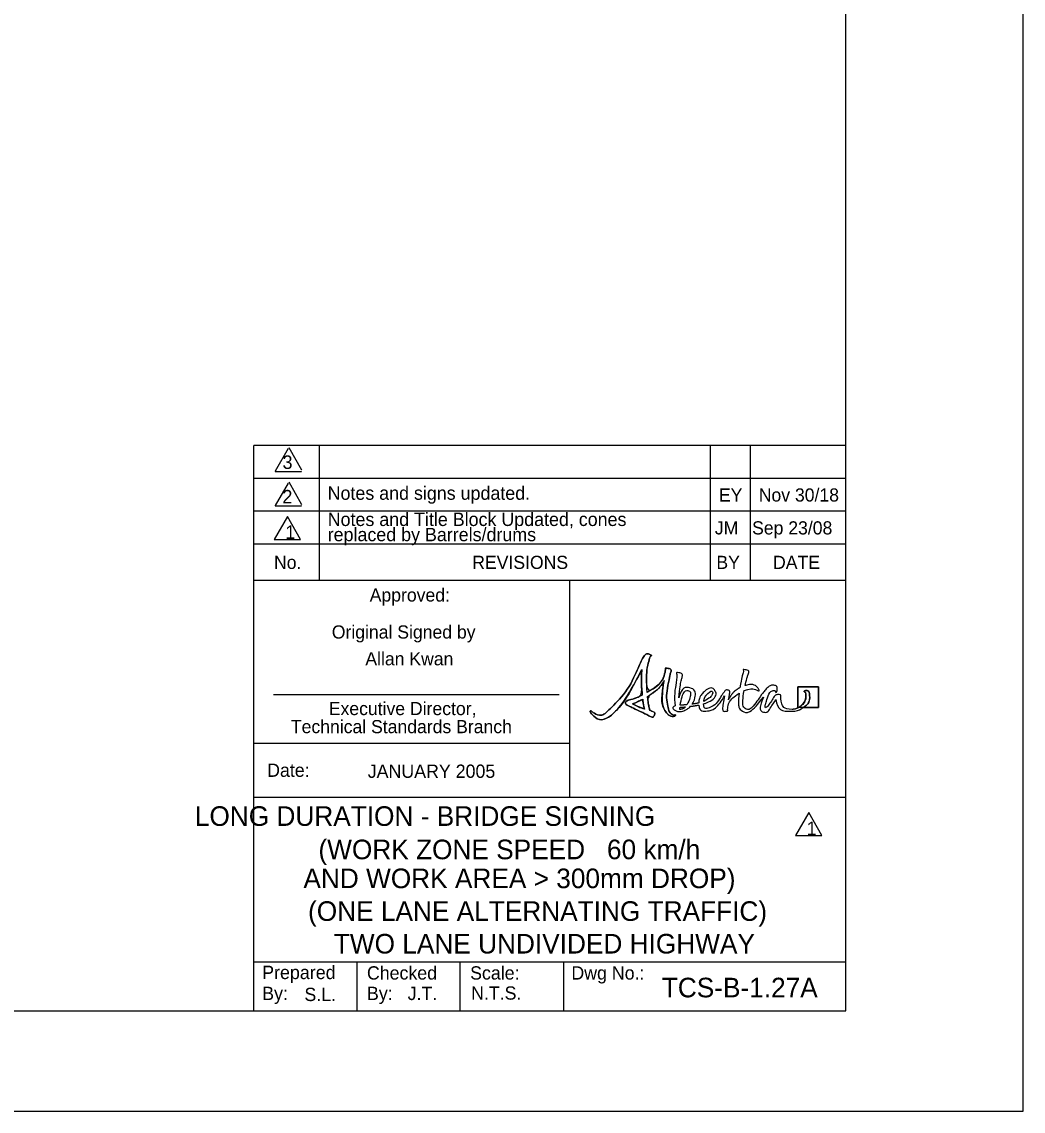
# Model space of a CAD drawing. Extents: x 2179 to 2395, y 134 to 413.
# Drawn here: x 2286.7 to 2394.7, y 133.8 to 251.3 of the extents above; entities that cross this region are included whole.
import ezdxf

# ---------------------------------------------------------------- set-up
doc = ezdxf.new("R2010")
doc.units = 0
for name, color, linetype in [('approved by', 7, 'Continuous'), ('Level 1', 7, 'Continuous'), ('Level 22', 7, 'Continuous'), ('Level 44', 7, 'Continuous'), ('Level 45', 7, 'Continuous'), ('Level 53', 7, 'Continuous'), ('Level 60', 7, 'Continuous'), ('Level 63', 7, 'Continuous'), ('Level 7', 7, 'Continuous')]:
    doc.layers.add(name, color=color, linetype=linetype)

# ---------------------------------------------------------------- blocks, each defined once
blk = doc.blocks.new('REV1')
at = {"layer": 'Level 1'}
blk.add_lwpolyline([(0.114, 1.689), (-1.305, -0.781), (1.533, -0.781)], close=True, dxfattribs=at)
blk.add_text('1', height=1.448, rotation=360, dxfattribs=at).set_placement((-0.113, -0.724))

msp = doc.modelspace()

# ---------------------------------------------------------------- linework, layer by layer
at = {"layer": 'Level 1'}
for p, q in [((2311.78, 144.57), (2311.78, 191.03)), ((2345.83, 191.03), (2345.83, 167.62)), ((2311.78, 173.47), (2345.83, 173.47)), ((2311.78, 167.62), (2375.62, 167.62)), ((2311.78, 149.89), (2375.62, 149.89)), ((2322.91, 144.57), (2322.91, 149.89)), ((2334.04, 144.57), (2334.04, 149.89)), ((2345.17, 149.89), (2345.17, 144.57))]:
    msp.add_line(p, q, dxfattribs=at)
at = {"layer": 'Level 22'}
msp.add_line((2327.24, 144.57), (2327.24, 144.57), dxfattribs=at)
at = {"layer": 'Level 44'}
for p, q in [((2375.65, 205.58), (2311.77, 205.58)), ((2375.65, 202.03), (2311.77, 202.03)), ((2375.65, 198.48), (2311.77, 198.48)), ((2375.65, 194.93), (2311.77, 194.93)), ((2311.78, 191.03), (2375.65, 191.03))]:
    msp.add_line(p, q, dxfattribs=at)
msp.add_lwpolyline([(2315.4, 197.91), (2313.98, 195.44), (2316.82, 195.44)], close=True, dxfattribs=at)
at = {"layer": 'Level 45'}
msp.add_line((2345.85, 191.03), (2345.85, 191.03), dxfattribs=at)
at = {"layer": 'Level 53'}
msp.add_line((2371.06, 177.31), (2370.51, 177.31), dxfattribs=at)
msp.add_lwpolyline([(2371.06, 177.31), (2372.67, 177.31), (2372.67, 179.54), (2370.44, 179.54), (2370.44, 177.31), (2370.51, 177.31)], dxfattribs=at)
for points, degree in [([(2357.07, 176.5), (2356.83, 176.53), (2356.52, 176.86), (2356.42, 177.4), (2356.25, 178.36), (2356.35, 179.32), (2356.64, 180.74), (2356.69, 181.01), (2356.87, 181.47), (2356.29, 181.56), (2356.1, 181.59), (2356.2, 181.5), (2356.15, 181.26), (2355.92, 180.2), (2355.06, 179.43), (2354.19, 178.92), (2354.1, 180.13), (2354.14, 181.48), (2354.36, 182.31), (2354.56, 183), (2354.79, 182.87), (2354.5, 183.02), (2354.2, 183.17), (2353.88, 182.97), (2353.62, 182.45), (2353.36, 181.93), (2352.17, 179.12), (2350.25, 177.22), (2349.28, 176.24), (2348.39, 176.74), (2348.21, 176.89), (2348.07, 177.02), (2348.02, 176.83), (2348.19, 176.64), (2348.99, 175.78), (2350.14, 176.27), (2350.56, 176.69), (2351.73, 177.86), (2353.08, 180.36), (2353.62, 181.42), (2353.57, 180.82), (2353.56, 179.82), (2353.67, 178.64), (2353.08, 178.36), (2352.55, 178.19), (2352.3, 178.12), (2352.02, 178.05), (2351.86, 177.94), (2351.85, 177.81), (2351.85, 177.68), (2352.03, 177.56), (2352.29, 177.43), (2352.76, 177.21), (2354.13, 176.56), (2354.47, 176.37), (2354.76, 176.2), (2354.9, 176.33), (2354.99, 176.51), (2355.1, 176.75), (2354.79, 176.88), (2354.49, 176.97), (2354.38, 177.37), (2354.29, 177.91), (2354.23, 178.5), (2354.92, 178.93), (2355.61, 179.5), (2356.01, 180.21), (2355.91, 179.62), (2355.65, 177.58), (2356.29, 176.73), (2356.43, 176.54), (2356.75, 176.33), (2357.05, 176.36), (2357.19, 176.37), (2357.27, 176.47), (2357.25, 176.5), (2357.24, 176.53), (2357.15, 176.49), (2357.07, 176.5)], 3), ([(2354.19, 178.92), (2354.1, 180.13), (2354.14, 181.48), (2354.36, 182.31), (2354.56, 183), (2354.79, 182.87), (2354.5, 183.02), (2354.2, 183.17), (2353.88, 182.97), (2353.62, 182.45), (2353.36, 181.93), (2352.17, 179.12), (2350.25, 177.22), (2349.28, 176.24), (2348.39, 176.74), (2348.21, 176.89), (2348.07, 177.02), (2348.02, 176.83), (2348.19, 176.64), (2348.99, 175.78), (2350.14, 176.27), (2350.56, 176.69), (2351.73, 177.86), (2353.08, 180.36), (2353.62, 181.42)], 3), ([(2353.62, 181.42), (2353.57, 180.82), (2353.56, 179.82), (2353.67, 178.64)], 2), ([(2357.07, 176.5), (2356.83, 176.53), (2356.52, 176.86), (2356.42, 177.4), (2356.25, 178.36), (2356.35, 179.32), (2356.64, 180.74), (2356.69, 181.01), (2356.87, 181.47), (2356.29, 181.56), (2356.1, 181.59), (2356.2, 181.5), (2356.15, 181.26), (2355.92, 180.2), (2355.06, 179.43), (2354.19, 178.92)], 3), ([(2357.61, 178.34), (2357.65, 178.91), (2357.74, 179.6), (2357.87, 180.24), (2357.93, 180.51), (2358.11, 180.98), (2357.53, 181.07), (2357.34, 181.1), (2357.37, 181.01), (2357.39, 180.76), (2357.41, 180.42), (2357.03, 178.38), (2357.23, 177.49)], 3), ([(2364.76, 179.68), (2364.83, 179.98), (2364.9, 180.28), (2364.98, 180.57), (2365.06, 180.84), (2365.28, 181.31), (2364.7, 181.4), (2364.52, 181.43), (2364.6, 181.34), (2364.54, 181.09), (2364.43, 180.63), (2364.29, 180.04), (2364.18, 179.45)], 3), ([(2354.23, 178.5), (2354.92, 178.93), (2355.61, 179.5), (2356.01, 180.21)], 2), ([(2356.01, 180.21), (2355.91, 179.62), (2355.65, 177.58), (2356.29, 176.73), (2356.43, 176.54), (2356.75, 176.33), (2357.05, 176.36), (2357.19, 176.37), (2357.27, 176.47), (2357.25, 176.5), (2357.24, 176.53), (2357.15, 176.49), (2357.07, 176.5)], 3), ([(2359.05, 177.68), (2359.46, 178.35), (2359.42, 179.26), (2358.82, 179.42), (2358.11, 179.59), (2357.76, 178.91), (2357.61, 178.34)], 3), ([(2357.76, 177.55), (2357.85, 178.27), (2358.23, 179.26), (2358.69, 179.1), (2358.96, 179.01), (2358.82, 178.17), (2358.47, 177.61)], 3), ([(2360.27, 177.7), (2360.37, 177.73), (2360.45, 177.76), (2360.53, 177.79), (2361.41, 178.19), (2361.71, 178.78), (2361.49, 179.14), (2361.28, 179.48), (2360.67, 179.37), (2360.19, 178.87), (2359.95, 178.62), (2359.77, 178.19), (2359.75, 177.8)], 3), ([(2362.95, 178.12), (2363, 178.39), (2363.09, 178.7), (2363.09, 178.91), (2363.1, 179.12), (2362.95, 179.17), (2362.89, 179.19), (2362.77, 179.22), (2362.62, 179.16), (2362.46, 178.95), (2362.11, 178.45), (2361.66, 177.66), (2360.98, 177.33), (2360.5, 177.1), (2360.28, 177.34), (2360.27, 177.7)], 3), ([(2360.74, 178.82), (2361.04, 179.1), (2361.19, 179.08), (2361.23, 179), (2361.31, 178.84), (2360.96, 178.28), (2360.29, 177.97)], 3), ([(2360.29, 177.97), (2360.35, 178.28), (2360.51, 178.61), (2360.74, 178.82)], 2), ([(2362.53, 178.56), (2362.48, 178.02), (2362.13, 176.85), (2362.73, 176.91), (2362.96, 176.93), (2362.86, 176.97), (2362.88, 177.17), (2362.93, 177.88), (2363.52, 178.48), (2364.1, 178.84)], 3), ([(2364.18, 179.45), (2363.71, 179.17), (2363.27, 178.72), (2362.95, 178.12)], 2), ([(2364.1, 178.84), (2364, 177.98), (2364.03, 177.21), (2364.42, 176.96), (2365.15, 176.51), (2366.17, 177.7), (2366.73, 178.42)], 3), ([(2369.82, 177.11), (2368.9, 177.11), (2368.66, 177.82), (2368.62, 178.17), (2368.59, 178.41), (2368.64, 178.75), (2368.24, 178.7), (2367.95, 178.67), (2367.7, 178.12), (2367.34, 177.66), (2367.03, 177.26), (2366.89, 177.29), (2366.97, 177.64), (2367.05, 178.07), (2367.41, 179.07), (2367.82, 179.14), (2368.01, 179.18), (2368.08, 178.84), (2368.17, 179.05), (2368.25, 179.26), (2368.17, 179.71), (2367.75, 179.71), (2367.45, 179.71), (2367.1, 179.4), (2366.8, 179.04), (2366.55, 178.73), (2365.27, 176.84), (2364.73, 177.24), (2364.47, 177.43), (2364.5, 178.21), (2364.65, 179.13)], 3), ([(2364.65, 179.13), (2365.29, 179.37), (2365.83, 179.29), (2366.13, 179.15), (2366.27, 179.08), (2366.3, 179.09), (2366.23, 179.25), (2366.14, 179.49), (2365.62, 179.87), (2364.82, 179.7), (2364.8, 179.69), (2364.78, 179.69), (2364.76, 179.68)], 3), ([(2370.44, 179.54), (2370.44, 179.54), (2370.44, 177.31), (2370.44, 177.31), (2370.44, 177.31), (2370.51, 177.31), (2370.51, 177.31), (2370.99, 177.6), (2371.32, 178.15), (2371.31, 178.61), (2371.31, 179), (2371.11, 178.98), (2371.13, 179.04), (2371.2, 179.2), (2371.69, 179.11), (2371.72, 178.55), (2371.74, 178.08), (2371.5, 177.62), (2371.06, 177.31), (2371.06, 177.31), (2372.67, 177.31), (2372.67, 177.31), (2372.67, 177.31), (2372.67, 179.54), (2372.67, 179.54), (2372.67, 179.54), (2370.44, 179.54), (2370.44, 179.54)], 3), ([(2370.51, 177.31), (2370.99, 177.6), (2371.32, 178.15), (2371.31, 178.61), (2371.31, 179), (2371.11, 178.98), (2371.13, 179.04), (2371.2, 179.2), (2371.69, 179.11), (2371.72, 178.55), (2371.74, 178.08), (2371.5, 177.62), (2371.06, 177.31)], 3), ([(2353.67, 178.64), (2353.08, 178.36), (2352.55, 178.19), (2352.3, 178.12), (2352.02, 178.05), (2351.86, 177.94), (2351.85, 177.81), (2351.85, 177.68), (2352.03, 177.56), (2352.29, 177.43), (2352.76, 177.21), (2354.13, 176.56), (2354.47, 176.37), (2354.76, 176.2), (2354.9, 176.33), (2354.99, 176.51), (2355.1, 176.75), (2354.79, 176.88), (2354.49, 176.97)], 3), ([(2352.6, 177.71), (2352.91, 177.82), (2353.3, 177.99), (2353.71, 178.21)], 2), ([(2352.6, 177.71), (2352.91, 177.82), (2353.3, 177.99), (2353.71, 178.21), (2353.77, 177.73), (2353.83, 177.39), (2353.9, 177.14), (2353.6, 177.25), (2353.16, 177.42), (2352.6, 177.71)], 3), ([(2353.9, 177.14), (2353.6, 177.25), (2353.16, 177.42), (2352.6, 177.71)], 2), ([(2353.71, 178.21), (2353.77, 177.73), (2353.83, 177.39), (2353.9, 177.14)], 2), ([(2354.49, 176.97), (2354.38, 177.37), (2354.29, 177.91), (2354.23, 178.5)], 2), ([(2357.23, 177.49), (2356.98, 177.41), (2356.87, 177.22), (2357.2, 177.02), (2357.42, 176.88), (2357.91, 176.84), (2358.41, 177.08), (2358.58, 177.17), (2358.74, 177.29), (2358.86, 177.44)], 3), ([(2358.47, 177.61), (2358.25, 177.59), (2358.01, 177.57), (2357.76, 177.55)], 2), ([(2358.86, 177.44), (2359.16, 177.47), (2359.47, 177.52), (2359.75, 177.58)], 2), ([(2359.75, 177.8), (2359.54, 177.75), (2359.31, 177.71), (2359.05, 177.68)], 2), ([(2359.75, 177.58), (2359.8, 177.18), (2360.06, 176.88), (2360.65, 176.94), (2361.5, 177.02), (2362.25, 178.06), (2362.53, 178.56)], 3), ([(2366.73, 178.42), (2366.44, 177.78), (2366.28, 176.95), (2366.71, 176.83), (2367.22, 176.68), (2367.61, 177.52), (2368.08, 178.16)], 3), ([(2368.08, 178.16), (2368.13, 177.7), (2368.44, 176.9), (2369.68, 176.9), (2370.23, 176.9), (2370.71, 177.06), (2371.06, 177.31)], 3), ([(2357.68, 177.12), (2357.71, 177.15), (2357.73, 177.19), (2357.73, 177.23), (2357.73, 177.26), (2357.74, 177.3), (2357.74, 177.33)], 3), ([(2357.88, 177.12), (2357.8, 177.11), (2357.74, 177.11), (2357.68, 177.12)], 2), ([(2357.74, 177.33), (2357.86, 177.33), (2358.06, 177.35), (2358.29, 177.37)], 2), ([(2358.29, 177.37), (2358.17, 177.24), (2358.03, 177.14), (2357.88, 177.12)], 2), ([(2370.51, 177.31), (2370.3, 177.19), (2370.07, 177.11), (2369.82, 177.11)], 2)]:
    msp.add_open_spline(points, degree=degree, dxfattribs=at)
at = {"layer": 'Level 60'}
for points in [[(2394.75, 412.76), (2178.75, 412.76), (2178.75, 133.76), (2394.75, 133.76)], [(2375.62, 401.95), (2188.75, 401.95), (2188.75, 144.57), (2375.62, 144.57)]]:
    msp.add_lwpolyline(points, close=True, dxfattribs=at)
at = {"layer": 'Level 63'}
for p, q in [((2311.78, 199.11), (2311.78, 205.58)), ((2318.87, 199.11), (2318.87, 205.58)), ((2360.98, 205.58), (2360.98, 191.03)), ((2365.29, 205.58), (2365.29, 191.03)), ((2311.78, 191.03), (2311.78, 199.11)), ((2318.87, 191.03), (2318.87, 199.11))]:
    msp.add_line(p, q, dxfattribs=at)
for points in [[(2315.48, 205.25), (2314.09, 202.82)], [(2316.96, 202.9), (2315.57, 205.33)], [(2314.09, 202.82), (2314.06, 202.78), (2316.9, 202.78), (2316.87, 202.82)], [(2315.48, 201.53), (2314.09, 199.11)], [(2316.96, 199.18), (2315.57, 201.61)], [(2314.09, 199.11), (2314.06, 199.06), (2316.9, 199.06), (2316.87, 199.11)]]:
    msp.add_lwpolyline(points, dxfattribs=at)
at = {"layer": 'Level 7'}
msp.add_line((2313.89, 178.72), (2344.69, 178.72), dxfattribs=at)

# ---------------------------------------------------------------- block references
at = {"layer": 'Level 1'}
msp.add_blockref('REV1', (2371.51, 164.28), dxfattribs=at)

# ---------------------------------------------------------------- texts
at = {"layer": 'approved by'}
for s, height, p in [('Original Signed by ', 1.4187, (2320.18, 184.75)), ('Allan Kwan', 1.419, (2323.8, 181.86))]:
    msp.add_text(s, height=height, dxfattribs=at).set_placement(p)
at = {"layer": 'Level 1'}
for s, height, p in [('Notes and signs updated.', 1.44, (2319.73, 199.72)), ('Date:', 1.433, (2313.21, 169.83)), ('Prepared', 1.44, (2312.67, 148.01)), ('Checked', 1.433, (2323.97, 147.96)), ('Scale:', 1.433, (2335.1, 147.96)), ('Dwg No.:', 1.433, (2346.02, 147.96)), ('By:', 1.44, (2312.67, 145.75)), ('By:   J.T.', 1.44, (2323.97, 145.75)), ('    N.T.S.   ', 1.4329, (2333.07, 145.79))]:
    msp.add_text(s, height=height, rotation=360, dxfattribs=at).set_placement(p)
msp.add_text('S.L.', height=1.433, dxfattribs=at).set_placement((2317.23, 145.64))
at = {"layer": 'Level 44'}
for s, height, p in [('3', 1.45, (2314.87, 203.05)), ('Nov 30/18', 1.419, (2366.23, 199.53)), ('2', 1.45, (2314.85, 199.33)), ('EY', 1.419, (2361.93, 199.53)), ('Sep 23/08', 1.419, (2365.51, 195.98)), ('1', 1.45, (2315.17, 195.5)), ('JM', 1.419, (2361.49, 195.98)), ('No.', 1.419, (2313.95, 192.26)), ('REVISIONS', 1.419, (2335.33, 192.26)), ('BY', 1.419, (2361.66, 192.26)), ('DATE', 1.419, (2367.77, 192.26))]:
    msp.add_text(s, height=height, rotation=360, dxfattribs=at).set_placement(p)
for s, height, p in [('         LONG DURATION - BRIDGE SIGNING        ', 2.115, (2298.34, 164.54)), ('(WORK ZONE SPEED   60 km/h', 2.1152, (2318.74, 160.94)), ('AND WORK AREA > 300mm DROP)', 2.1152, (2317.12, 157.82)), ('(ONE LANE ALTERNATING TRAFFIC)', 2.1152, (2317.62, 154.29)), ('TWO LANE UNDIVIDED HIGHWAY', 2.1152, (2320.4, 150.77))]:
    msp.add_text(s, height=height, dxfattribs=at).set_placement(p)
at = {"layer": 'Level 60'}
for s, p in [('Notes and Title Block Updated, cones ', (2319.74, 196.89)), ('replaced by Barrels/drums', (2319.74, 195.25))]:
    msp.add_text(s, height=1.44, rotation=360, dxfattribs=at).set_placement(p)
for s, height, p in [('JANUARY 2005', 1.434, (2324.06, 169.72)), ('TCS-B-1.27A', 2.115, (2355.77, 146.04))]:
    msp.add_text(s, height=height, dxfattribs=at).set_placement(p)
at = {"layer": 'Level 7'}
for s, height, p in [('Approved:', 1.419, (2324.27, 188.74)), ('Executive Director,', 1.4187, (2319.86, 176.49)), ('Technical Standards Branch', 1.4187, (2315.77, 174.54))]:
    msp.add_text(s, height=height, dxfattribs=at).set_placement(p)

doc.saveas('drawing.dxf')
